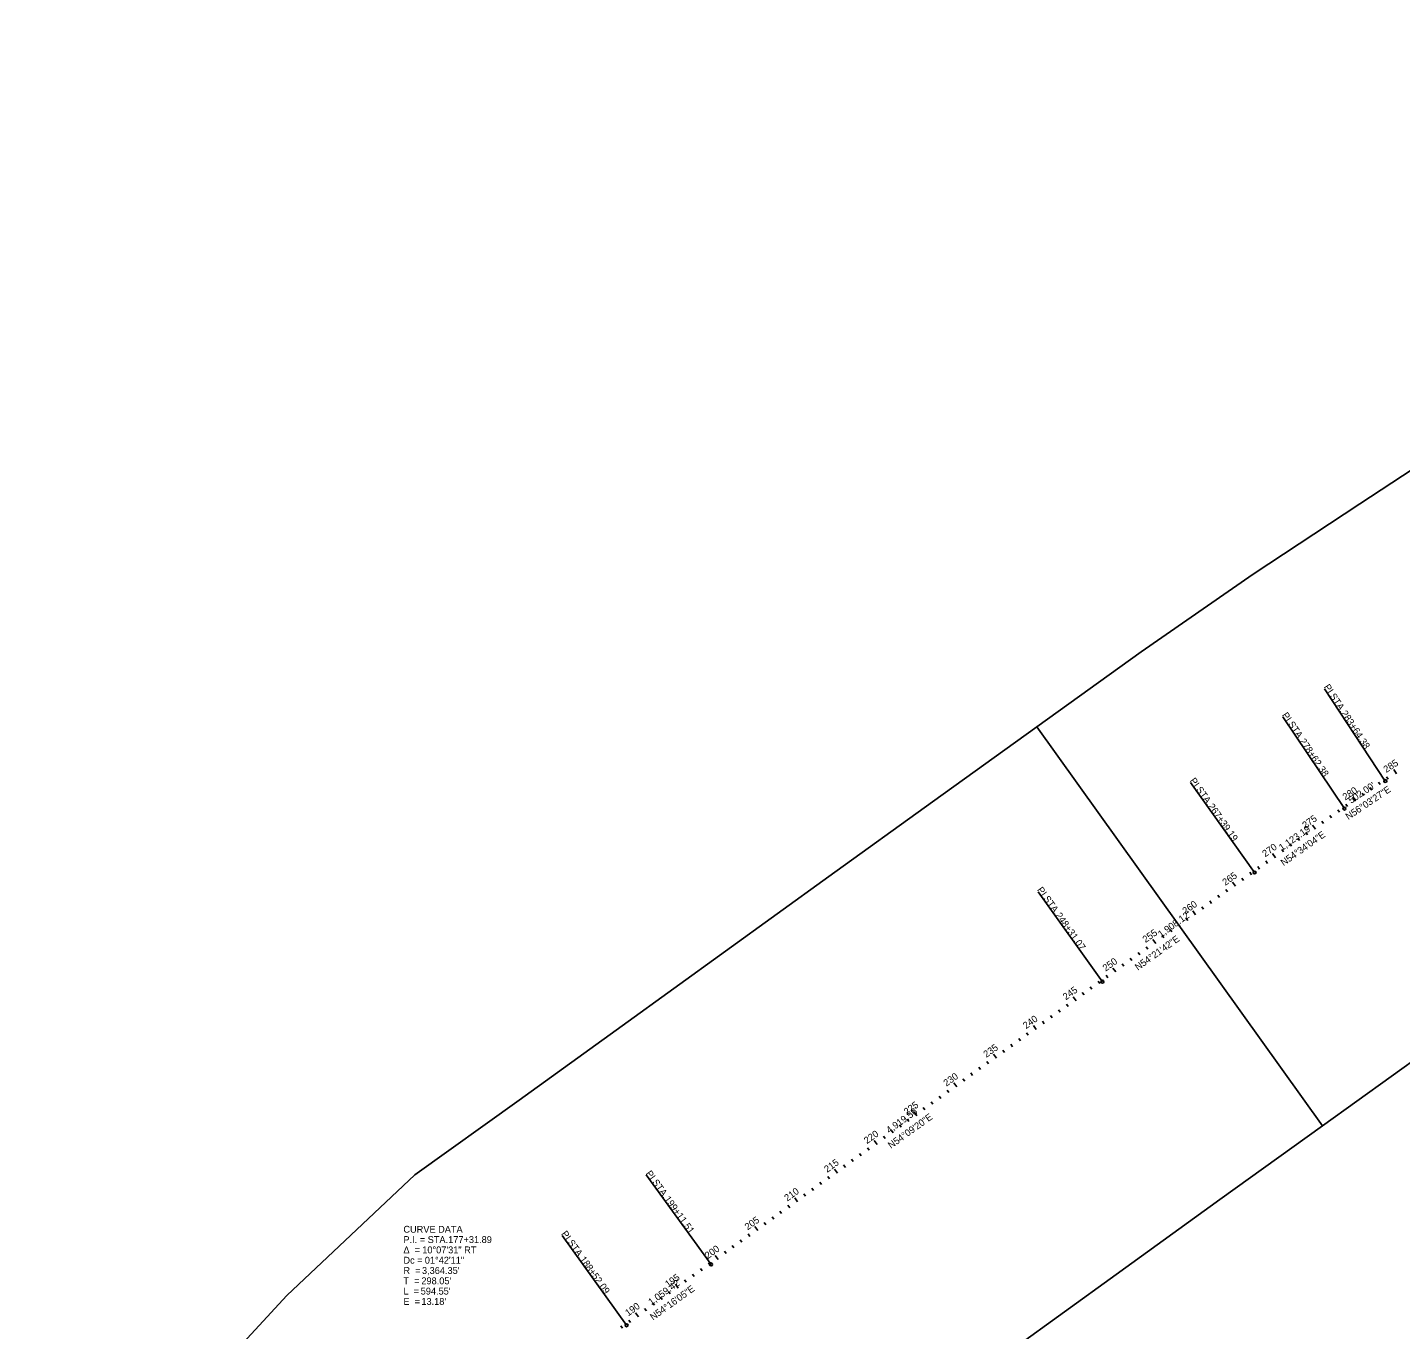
# Model space of a CAD drawing. Extents: x 187058 to 230449, y 263308 to 297406.
# Drawn here: x 195008 to 208999, y 279748 to 293010 of the extents above; entities that cross this region are included whole.
import ezdxf

# ---------------------------------------------------------------- set-up
doc = ezdxf.new("R2010")
doc.units = 0
for name, color, linetype in [('BR_X_Gen_Approach_Slab', 7, 'Continuous'), ('BR_X_SV_Deck_Top', 7, 'Continuous'), ('PV_X_Curb', 7, 'Continuous'), ('PV_X_Walk', 7, 'Continuous'), ('RD_X_GR_Lt', 7, 'Continuous'), ('SH_Named_Boundary', 7, 'Continuous')]:
    doc.layers.add(name, color=color, linetype=linetype)

msp = doc.modelspace()

# ---------------------------------------------------------------- linework, layer by layer
at = {"layer": 'BR_X_SV_Deck_Top'}
for p, q in [((208957, 285409), (208929, 285451)), ((208790, 285299), (208773, 285324)), ((208873, 285354), (208857, 285379)), ((208541, 285131), (208513, 285173)), ((208624, 285187), (208607, 285212)), ((208707, 285243), (208690, 285268)), ((208376, 285018), (208359, 285043)), ((208458, 285075), (208442, 285100)), ((208132, 284844), (208103, 284885)), ((208213, 284902), (208196, 284927)), ((208295, 284960), (208277, 284985)), ((207969, 284728), (207951, 284753)), ((208050, 284786), (208033, 284811)), ((207724, 284554), (207695, 284595)), ((207806, 284612), (207788, 284637)), ((207887, 284670), (207870, 284695)), ((207561, 284438), (207544, 284463)), ((207643, 284496), (207626, 284521)), ((207317, 284264), (207288, 284304)), ((207399, 284322), (207381, 284346)), ((207480, 284380), (207463, 284405)), ((207155, 284147), (207137, 284172)), ((207236, 284205), (207219, 284230)), ((206992, 284031), (206975, 284055)), ((207074, 284089), (207056, 284113)), ((206749, 283856), (206731, 283880)), ((206830, 283914), (206812, 283939)), ((206911, 283972), (206882, 284013)), ((206586, 283739), (206569, 283764)), ((206667, 283798), (206650, 283822)), ((206424, 283623), (206406, 283647)), ((206505, 283681), (206476, 283722)), ((206180, 283448), (206162, 283472)), ((206261, 283506), (206243, 283531)), ((206342, 283565), (206325, 283589)), ((206017, 283331), (206000, 283356)), ((206098, 283390), (206069, 283430)), ((205774, 283156), (205756, 283180)), ((205855, 283215), (205837, 283239)), ((205936, 283273), (205918, 283297)), ((205612, 283039), (205594, 283063)), ((205693, 283097), (205663, 283138)), ((205450, 282922), (205432, 282946)), ((205531, 282980), (205513, 283005)), ((205206, 282746), (205189, 282770)), ((205287, 282805), (205258, 282845)), ((205369, 282863), (205351, 282888)), ((205044, 282629), (205027, 282653)), ((205125, 282688), (205108, 282712)), ((204801, 282453), (204784, 282478)), ((204882, 282512), (204853, 282552)), ((204963, 282570), (204946, 282595)), ((204639, 282336), (204621, 282361)), ((204720, 282395), (204702, 282419)), ((204477, 282219), (204448, 282260)), ((204558, 282278), (204540, 282302)), ((204234, 282043), (204216, 282068)), ((204315, 282102), (204297, 282126)), ((204396, 282161), (204378, 282185)), ((204072, 281926), (204042, 281967)), ((204153, 281985), (204135, 282009)), ((203828, 281751), (203811, 281775)), ((203909, 281809), (203892, 281833)), ((203990, 281868), (203973, 281892)), ((203666, 281633), (203637, 281674)), ((203747, 281692), (203730, 281716)), ((203504, 281516), (203487, 281541)), ((203585, 281575), (203568, 281599)), ((203261, 281341), (203232, 281381)), ((203342, 281399), (203324, 281424)), ((203423, 281458), (203405, 281482)), ((203099, 281224), (203081, 281248)), ((203180, 281282), (203162, 281306)), ((202856, 281048), (202826, 281088)), ((202937, 281106), (202919, 281131)), ((203018, 281165), (203000, 281189)), ((202693, 280931), (202676, 280955)), ((202775, 280989), (202757, 281014)), ((202450, 280755), (202421, 280796)), ((202531, 280814), (202514, 280838)), ((202612, 280872), (202595, 280897)), ((202288, 280638), (202271, 280662)), ((202369, 280697), (202352, 280721)), ((202126, 280521), (202109, 280545)), ((202207, 280579), (202190, 280604)), ((201964, 280404), (201946, 280428)), ((202045, 280462), (202016, 280503)), ((201720, 280229), (201703, 280253)), ((201802, 280287), (201784, 280311)), ((201883, 280345), (201865, 280370)), ((201558, 280112), (201541, 280136)), ((201639, 280170), (201610, 280211)), ((201315, 279937), (201297, 279961)), ((201396, 279995), (201378, 280019)), ((201477, 280053), (201459, 280078)), ((201152, 279820), (201135, 279844)), ((201233, 279878), (201204, 279919)), ((201071, 279762), (201053, 279786))]:
    msp.add_line(p, q, dxfattribs=at)
at = {"layer": 'PV_X_Walk'}
for p, q in [((208844, 285335), (208225, 286274)), ((208427, 285054), (207799, 285988)), ((207512, 284403), (206860, 285320)), ((205961, 283291), (205306, 284206)), ((201973, 280411), (201314, 281322)), ((201113, 279792), (200456, 280705))]:
    msp.add_line(p, q, dxfattribs=at)
for centre in [(208844, 285335), (208427, 285054), (207512, 284403), (205961, 283291), (201973, 280411), (201113, 279792)]:
    msp.add_circle(centre, 15, dxfattribs=at)
at = {"layer": 'SH_Named_Boundary'}
for points in [[(205292, 285888), (208205, 281824), (209255, 282575), (210248, 283266), (211334, 283981), (212420, 284696), (213505, 285411), (214637, 286160), (215714, 286908), (216759, 287632), (217237, 287847), (218483, 288219), (217055, 293010), (215810, 292639), (213943, 291764), (212852, 291008), (211792, 290272), (210756, 289587), (209670, 288872), (208584, 288157), (207498, 287442), (206357, 286649)], [(195008, 277232), (198673, 273830), (199555, 274787), (200443, 275748), (201321, 276698), (201882, 277272), (202937, 278024), (203995, 278787), (205049, 279548), (206103, 280310), (207157, 281071), (208205, 281824), (205292, 285888), (204229, 285124), (203175, 284363), (202121, 283601), (201067, 282840), (200017, 282083), (198955, 281325), (197651, 280094), (196765, 279135), (195888, 278186)]]:
    msp.add_lwpolyline(points, close=True, dxfattribs=at)

# ---------------------------------------------------------------- texts
at = {"layer": 'BR_X_Gen_Approach_Slab'}
for s, rotation, p in [("502.00'", 33.9425, (208496, 285102)), ("1,123.19'", 35.4323, (207790, 284620)), ("1,908.12'", 35.6384, (206558, 283738)), ("4,919.56'", 35.8444, (203789, 281741)), ("1,059.42'", 35.7319, (201365, 279992))]:
    msp.add_text(s, height=70, rotation=rotation, dxfattribs=at).set_placement(p)
at = {"layer": 'BR_X_SV_Deck_Top'}
for s, rotation, p in [('285', 33.3617, (208853, 285416)), ('280', 33.9425, (208437, 285136)), ('275', 35.4323, (208028, 284847)), ('270', 35.4323, (207620, 284557)), ('265', 35.6384, (207214, 284266)), ('260', 35.6384, (206807, 283974)), ('255', 35.6384, (206401, 283684)), ('250', 35.6384, (205994, 283392)), ('245', 35.8444, (205589, 283100)), ('240', 35.8444, (205183, 282806)), ('235', 35.8444, (204779, 282514)), ('230', 35.8444, (204372, 282221)), ('225', 35.8444, (203968, 281929)), ('220', 35.8444, (203562, 281635)), ('215', 35.8444, (203157, 281343)), ('210', 35.8444, (202751, 281050)), ('205', 35.8444, (202347, 280757)), ('200', 35.8444, (201941, 280464)), ('195', 35.7319, (201536, 280173)), ('190', 35.7319, (201129, 279880))]:
    msp.add_text(s, height=70, rotation=rotation, dxfattribs=at).set_placement(p)
at = {"layer": 'PV_X_Curb'}
for s, p in [('CURVE DATA', (198839, 280734)), ('P.I. = STA. ', (198839, 280629)), ('177+31.89', (199295, 280629)), ('Δ  = ', (198839, 280524)), ('10°07\'31" RT', (199031, 280524)), ('Dc = ', (198839, 280419)), ('R  = ', (198839, 280314)), ("3,364.35'", (199028, 280314)), ('01°42\'11"', (199057, 280419)), ('T  = ', (198839, 280209)), ("298.05'", (199022, 280209)), ('L  = ', (198839, 280104)), ("594.55'", (199015, 280104)), ('E  = ', (198839, 279999)), ("13.18'", (199022, 279999))]:
    msp.add_text(s, height=70, dxfattribs=at).set_placement(p)
at = {"layer": 'PV_X_Walk'}
for s, rotation, p in [('PI', 303.3617, (208214, 286293)), (' STA. ', 303.3617, (208260, 286222)), ('PI', 303.9425, (207787, 286006)), ('283+64.38', 303.3617, (208390, 286025)), (' STA. ', 303.9425, (207835, 285936)), ('278+62.38', 303.9425, (207967, 285740)), ('PI', 305.4323, (206848, 285338)), (' STA. ', 305.4323, (206897, 285269)), ('267+39.19', 305.4323, (207034, 285076)), ('PI', 305.6384, (205292, 284226)), (' STA. ', 305.6384, (205342, 284157)), ('248+31.07', 305.6384, (205480, 283965)), ('PI', 305.8444, (201305, 281337)), (' STA. ', 305.8444, (201355, 281268)), ('199+11.51', 305.8444, (201493, 281077)), ('PI', 305.7319, (200444, 280723)), (' STA. ', 305.7319, (200494, 280654)), ('188+52.09', 305.7319, (200632, 280463))]:
    msp.add_text(s, height=70, rotation=rotation, dxfattribs=at).set_placement(p)
at = {"layer": 'RD_X_GR_Lt'}
for s, rotation, p in [('N56°03\'27"E', 33.9425, (208467, 284936)), ('N54°34\'04"E', 35.4323, (207808, 284466)), ('N54°21\'42"E', 35.6384, (206323, 283402)), ('N54°09\'20"E', 35.8444, (203807, 281587)), ('N54°16\'05"E', 35.7319, (201383, 279838))]:
    msp.add_text(s, height=70, rotation=rotation, dxfattribs=at).set_placement(p)

doc.saveas('drawing.dxf')
